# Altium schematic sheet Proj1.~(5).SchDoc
size A4
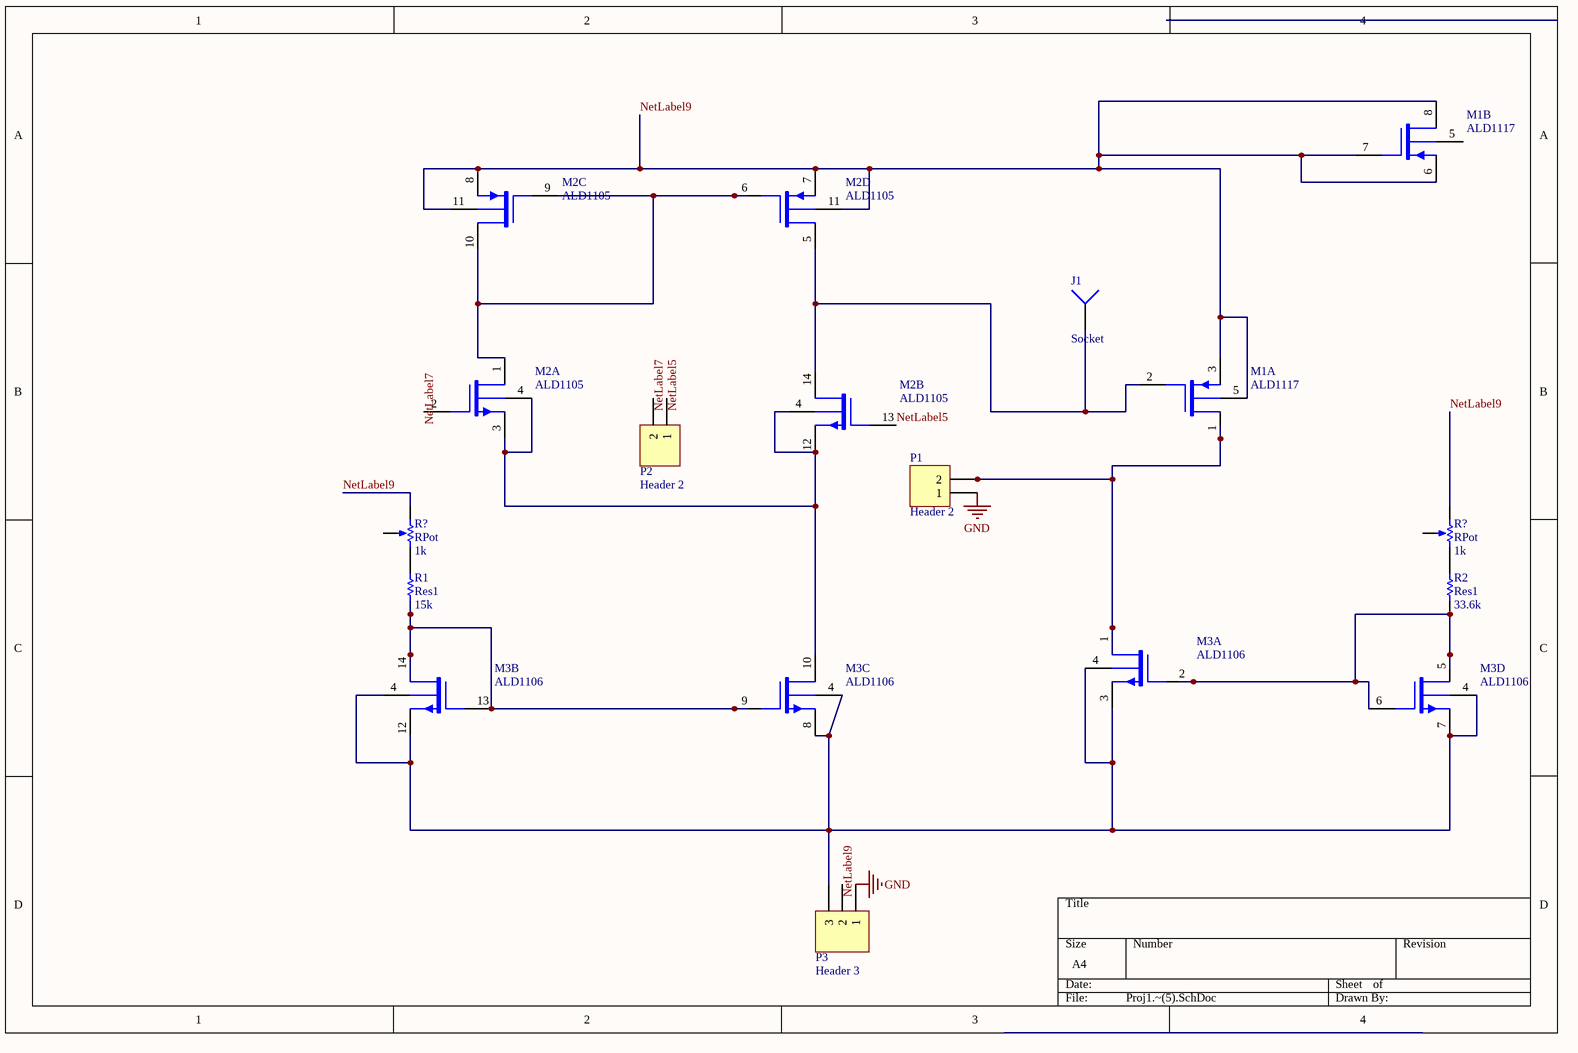
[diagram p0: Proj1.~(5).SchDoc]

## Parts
(Parts that share a designator on the sheet are numbered #1, #2 ... from top to bottom, then left to right.)
J1  Socket  [PIN1]
M1  ALD1117  [DIP-8]  (parts A,B of 2)
M2  ALD1105  [DIP-14]  (parts A,B,C,D of 4)
M3  ALD1106  [DIP-14]  (parts A,B,C,D of 4)
P1  Header 2  [HDR1X2]
P2  Header 2  [HDR1X2]
P3  Header 3  [HDR1X3]
R1  Res1  value 15k  [AXIAL-0.3]
R2  Res1  value 33.6k  [AXIAL-0.3]
R?#1  RPot  value 1k  [VR5]
R?#2  RPot  value 1k  [VR5]

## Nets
GND: P1.1 P3.1
NetLabel5: M2.13(GN2)
NetLabel9: M1.3(SP1) M1.5(V+) M1.6(SP2) M1.7(GP2) M1.8(DP2) M2.7(SP1) M2.8(SP2) M2.11(V+) R?#1.1(TOP) R?#2.1(TOP)
NetJ1_1: J1.1 M1.2(GP1) M2.5(DP1) M2.14(DN2)
NetM1_1: M1.1(DP1) M3.1(DN1) P1.2
NetM2_1: M2.1(DN1) M2.6(GP1) M2.9(GP2) M2.10(DP2)
NetM2_3: M2.3(SN1) M2.4(V-) M2.12(SN2) M3.10(DN3)
NetM3_2: M3.2(GN1) M3.5(DN4) M3.6(GN4) R2.1
NetM3_3: M3.3(SN1) M3.4(V-) M3.7(SN4) M3.8(SN3) M3.12(SN2) P3.3
NetM3_9: M3.9(GN3) M3.13(GN2) M3.14(DN2) R1.1
NetR1_2: R1.2 R?#1.3(BOT)
NetR2_2: R2.2 R?#2.3(BOT)

Not connected (* = marked no-connect by the designer): M2 2(GN1); P2 1 2; P3 2; R?#1 2(TAP); R?#2 2(TAP)

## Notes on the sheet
- Labels drawn without touching a wire or pin: NetLabel5, NetLabel7, NetLabel9

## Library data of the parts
M1 = ALD1117: Dual P-channel matched MOSFET array
M2 = ALD1105: Dual P-channel and dual N-channel matched MOSFET array
M3 = ALD1106: Quad N-channel matched MOSFET array
P1 P2 = Header 2: Header, 2-Pin
P3 = Header 3: Header, 3-Pin
R1 R2 = Res1: Resistor
R?#1 R?#2 = RPot: Potentiometer; Sim Note: Enter the Resistance value and the set point into parameter fields.; Set Position: 0.5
